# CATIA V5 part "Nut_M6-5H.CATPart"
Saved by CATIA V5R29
Part number: ReM6
Bounding box of the stored display mesh (mm): x -5 to 5, y -5.774 to 5.774, z -2.5 to 2.5
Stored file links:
  C:\Users\Administrator\Desktop\프로젝트\Boxfold\Foot\Nut_M6-5H.CATPart
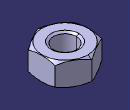
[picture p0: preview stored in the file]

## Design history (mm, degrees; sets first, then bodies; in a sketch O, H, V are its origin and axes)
Body1 (main body)
  Sketch1 on xy-plane, origin (0, 0, 0), H (1, 0, 0), V (0, 1, 0)
    point P1 (5, 0)
    construction circle A1 centre (0, 0) radius 5.7735
    construction circle A2 centre (0, 0) radius 5
    point P2 (5, -2.8868)
    point P3 (5, 2.8868)
    point P4 (0, 5.7735)
    point P5 (-5, 2.8868)
    point P6 (-5, -2.8868)
    point P7 (0, -5.7735)
    line L1 (5, -2.8868) -> (5, 2.8868)
    line L2 (5, 2.8868) -> (0, 5.7735)
    line L3 (0, 5.7735) -> (-5, 2.8868)
    line L4 (-5, 2.8868) -> (-5, -2.8868)
    line L5 (-5, -2.8868) -> (0, -5.7735)
    line L6 (0, -5.7735) -> (5, -2.8868)
    construction line L7 (0, 0) -> (5, 0)
    radius A2 = 5
    coincidence: A1 P2, A1 P3, A1 P4, A1 P5, A1 P6, A1 P7
    tangency: A2 L1, A2 L2, A2 L3, A2 L4, A2 L5, A2 L6
    midpoint: P1 L1
    horizontal: L7 H
  Pad1: profile Sketch1, direction (0, 0, 1), length 2.5, mirrored extent
  Sketch2 on yz-plane, origin (0, 0, 0), H (0, 1, 0), V (0, 0, 1)
    point P1 (4.9, 2.5)
    line L1 (4.9, 2.5) -> (5.7735, 2.5)
    point P2 (5.7735, 2.5)
    line L2 (5.7735, 2.5) -> (5.7735, 1.9957)
    point P3 (5.7735, 1.9957)
    line L3 (5.7735, 1.9957) -> (4.9, 2.5)
    reference projected point E1 (5.7735, 2.5) from vertex [face of Pad1 from Sketch1.L3 | end face of Pad1 | face of Pad1 from Sketch1.L2]
    point P4 (4.9, -2.5)
    point P5 (5.7735, -2.5)
    point P6 (5.7735, -1.9957)
    line L4 (4.9, -2.5) -> (5.7735, -2.5)
    line L5 (5.7735, -2.5) -> (5.7735, -1.9957)
    line L6 (5.7735, -1.9957) -> (4.9, -2.5)
    distance P1 V = 4.9
    angle L3 L1 = 30
    horizontal: L1 H
    vertical: L2 V
    coincidence: E1 P2
    symmetry: P1 P4 H, P2 P5 H, P3 P6 H, L1 L4 H, L2 L5 H, L3 L6 H
  Groove1: profile Sketch2, axis Z axis, angle 360
  Sketch3 on end face of Pad1, origin (-2.3341, 3.0327, 2.5), H (1, 0, 0), V (0, 1, 0)
    point P1 (2.3341, -3.0327)
    reference projected circle E1 centre (2.3341, -3.0327) radius 4.9 from edge [face of Groove1 from Sketch2.L3 | end face of Pad1]
    concentricity: E1 P1
  Hole1: placed by Sketch3, at (0, 0, 2.5) direction (0, 0, -1), diameter 4.917, through (limit type 3), threaded "M6", thread diameter 6, thread depth 5, pitch 1
  Chamfer1: length 0.5, angle 30, on face of Hole1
